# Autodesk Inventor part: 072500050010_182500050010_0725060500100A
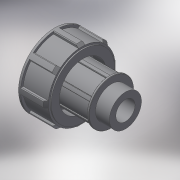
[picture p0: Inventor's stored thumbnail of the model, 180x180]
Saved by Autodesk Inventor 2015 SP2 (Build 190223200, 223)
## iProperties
Created: 2017-04
Part Number: 072500050010_182500050010_0725060500100A
Material: Generic
Description: PLASSON THREADED ADAPTOR 50-1"
Document SubType Name: Modeling
Designer: KIM
Density: 1 g/cm^3
Appearance: Default
Author: KIM
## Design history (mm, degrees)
derived "07250.ipt"
feature "Solid1::07250.ipt"
tag "TaggingFeature1"
body "Solid1"
other parameters: "d1" = 33.249, "d2" = 102, "d6" = 96, "d7" = 89.28, "d8" = 76.8, "d10" = 56.5233, "d12" = 19.9494, "d13" = 26.5992, "d14" = 23, "d15" = 72, "d16" = 3.06, "d17" = 40.8, "d19" = 24, "d24" = 6.6498, "d25" = 3.3249, "d27" = 0, "d28" = 2.65992, "d31" = 0.66498, "d35" = 360 deg, "d41" = 29.337, "d56" = 55, "d57" = 5, "d58" = 2.5, "d60" = 0, "d61" = 0.33249, "d64" = 0.33249, "d68" = 360 deg, "R_" = 33.249, "E_" = 96, "H_" = 102
